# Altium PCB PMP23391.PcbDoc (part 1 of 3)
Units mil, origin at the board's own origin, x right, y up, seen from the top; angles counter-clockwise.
Board outline 5500 x 3250 mil, 2 copper layers (Top Layer, Bottom Layer), stack 62 mil thick; 163 components, 101 nets, 543 pads, 307 vias.
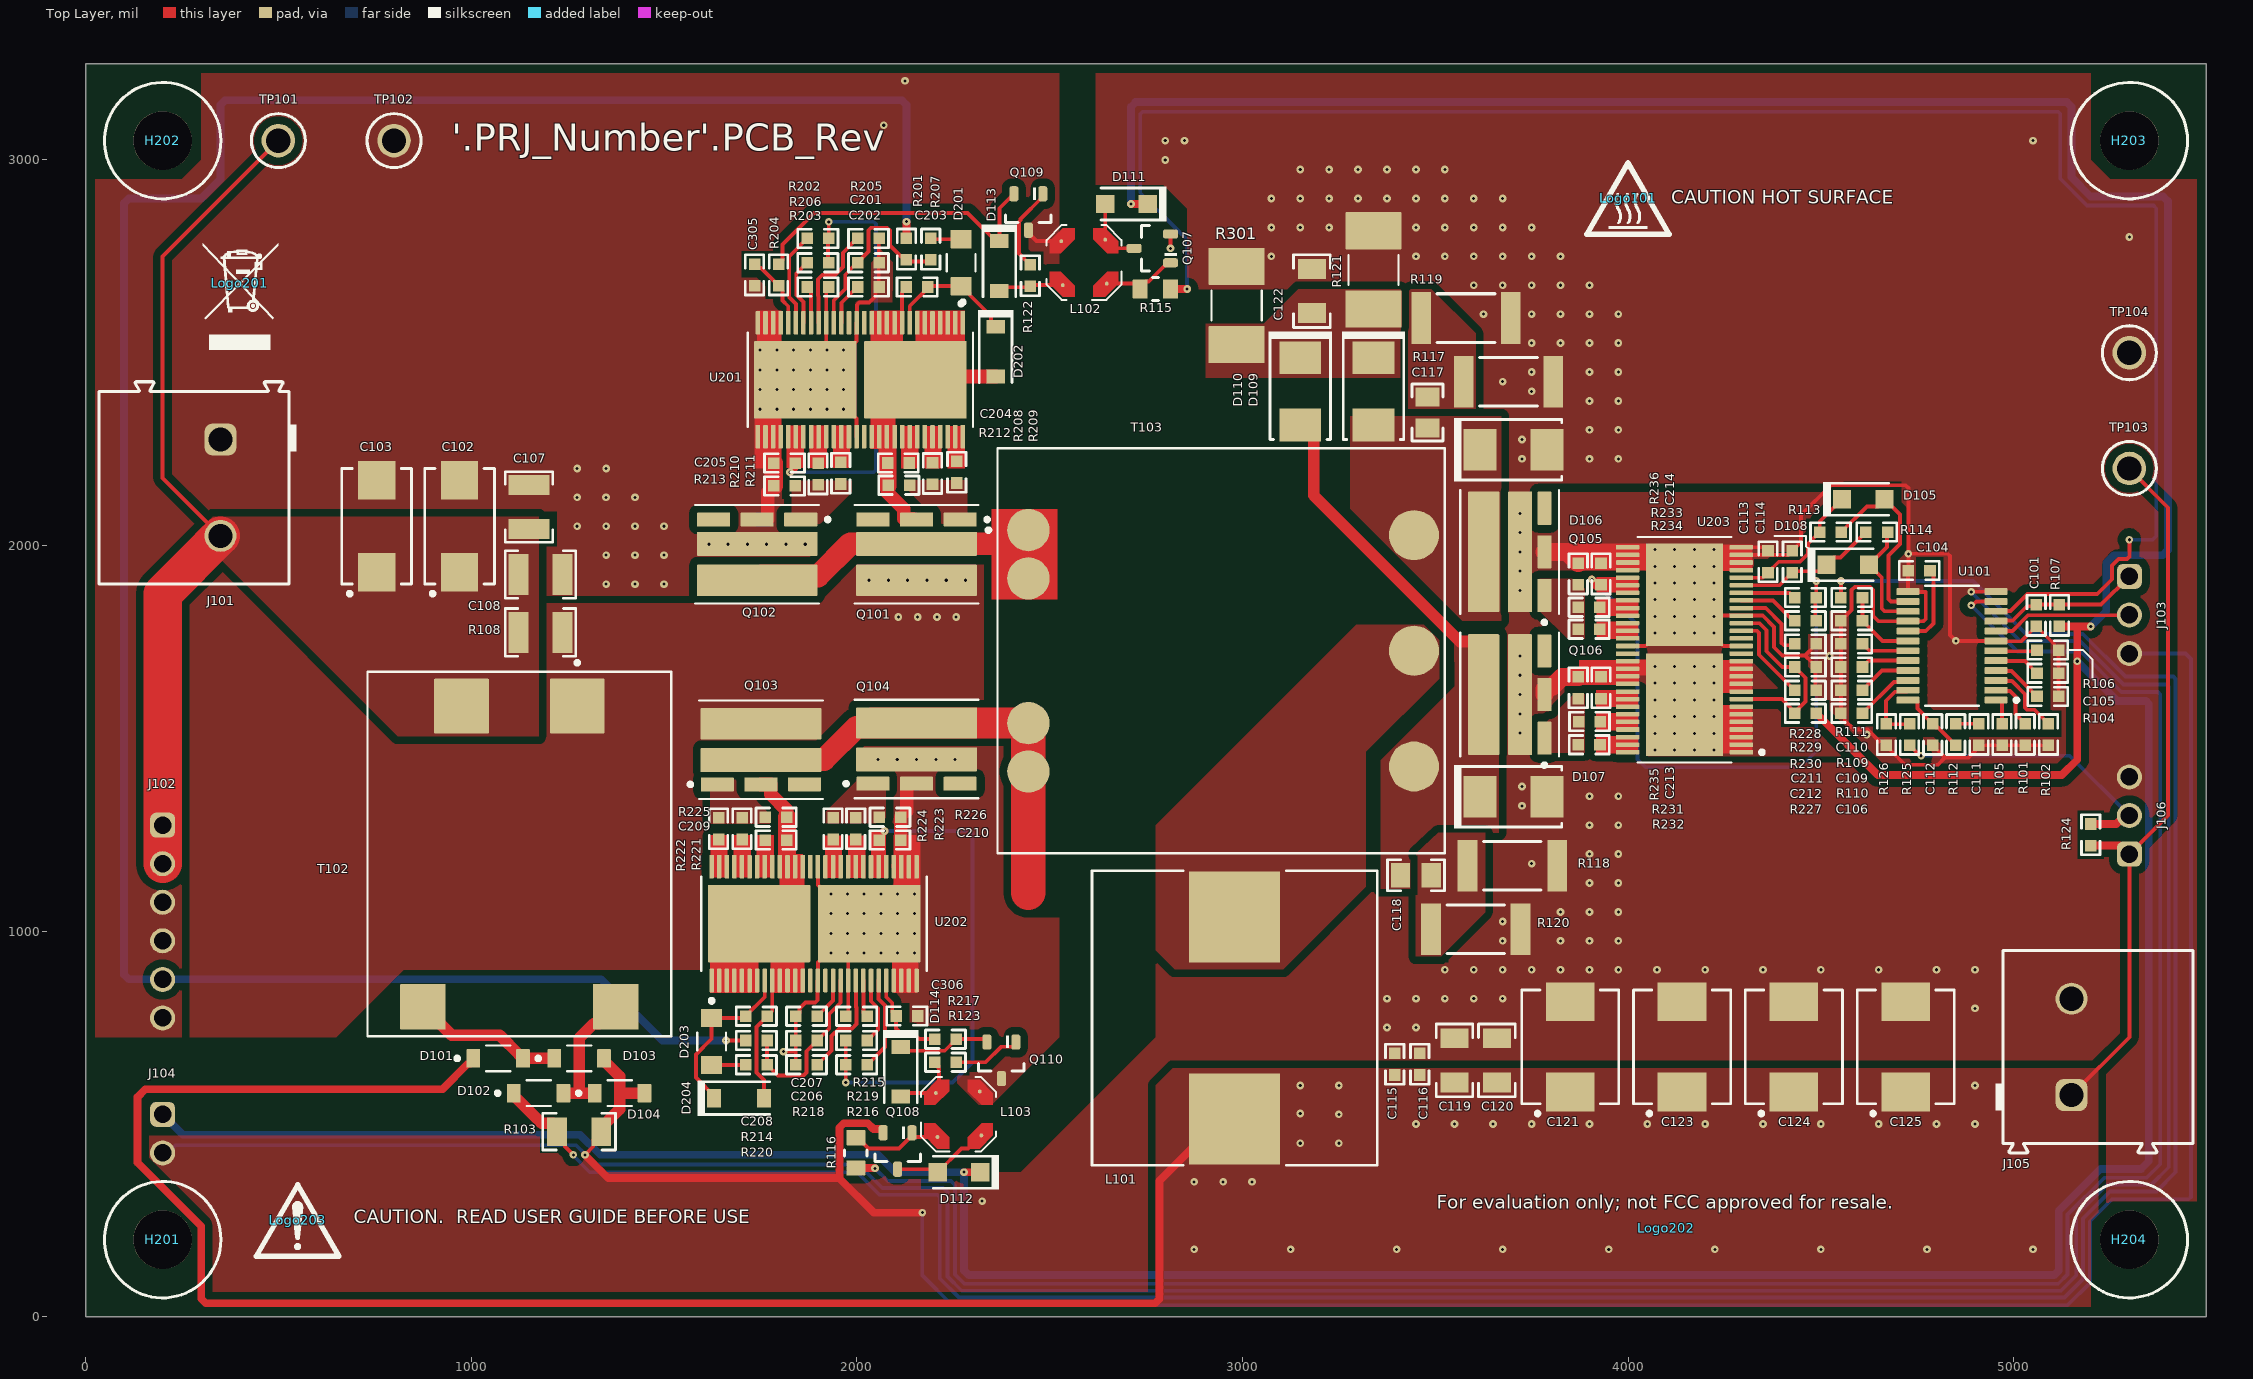
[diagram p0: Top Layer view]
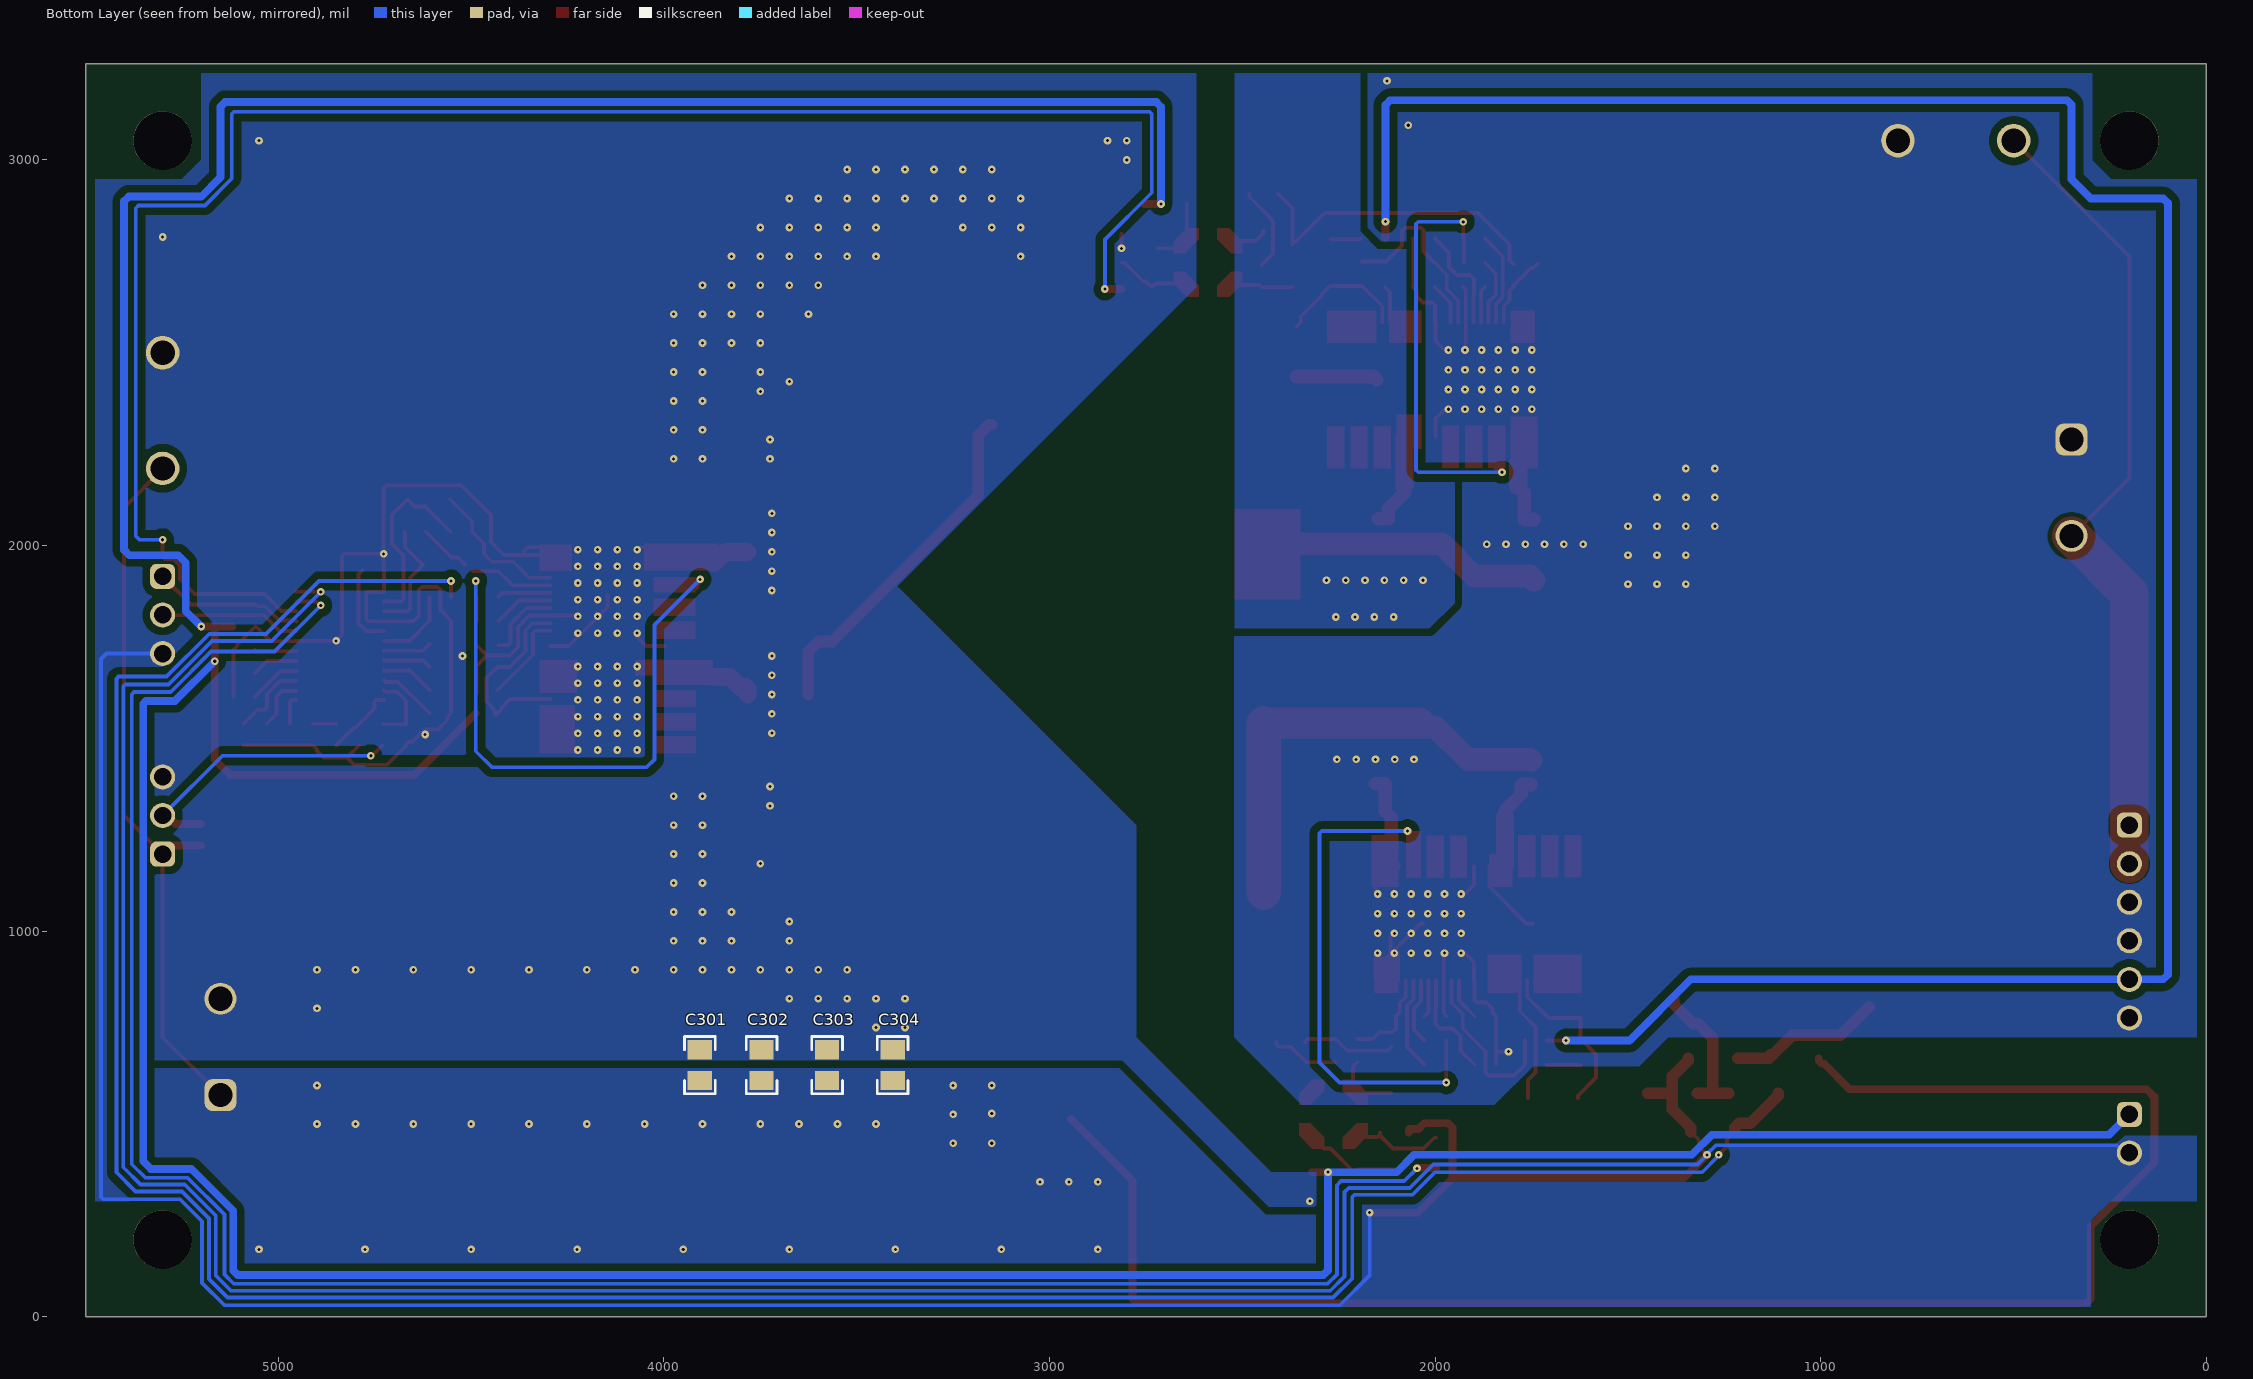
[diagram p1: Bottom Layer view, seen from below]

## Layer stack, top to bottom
Top Solder: solder mask 0.4, Solder Resist, Dk 3.5
Top Layer: signal copper 1.4
Dielectric1: core 59.2, FR-4 High Tg, Dk 4.8
Bottom Layer: signal copper 1.4
Bottom Solder: solder mask 0.4, Solder Resist, Dk 3.5

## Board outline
0,0 0,3250 5500,3250 5500,0

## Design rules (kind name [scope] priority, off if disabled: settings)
AcuteAngle [All] p1: minimum=4.50000000000000E+0001 checktracksonly=FALSE
AssemblyTestPointUsage [All] p1: valid=2
BoardOutlineClearance BoardOutlineClearance_MountingHoles [OnCopper and InComponentClass('Mounting Holes')] p1: gap=25 ignorepadtopadclearanceinfootprint=FALSE
BoardOutlineClearance BoardOutlineClearance_Poly [OnCopper and InPoly] p2: gap=25 ignorepadtopadclearanceinfootprint=FALSE
BoardOutlineClearance [OnCopper and Not InComponentClass('Logo') and not InComponentClass('FiducialMark') and not InRegion(1000,500,4000,800)] p3: gap=25 ignorepadtopadclearanceinfootprint=FALSE
Clearance Clearance_2 [InNetClass('HV') vs Not InNetClass('HV')] p1: gap=60 ignorepadtopadclearanceinfootprint=FALSE
Clearance Clearance_1 [InNetClass('MV') vs Not InNetClass('MV')] p2: gap=30 ignorepadtopadclearanceinfootprint=FALSE
Clearance Clearance_Keepouts [((IsTrack Or IsArc) And Not InPoly) And IsFree and IsKeepOut vs ((IsTrack Or IsArc) And Not InPoly) And IsFree and IsKeepOut] p3: gap=0 ignorepadtopadclearanceinfootprint=FALSE
Clearance Clearance_BoardEdge_MountingHoles [OnCopper and InComponentClass('Mounting Holes') vs IsKeepOut] p4: gap=40 ignorepadtopadclearanceinfootprint=FALSE except(0: Arc-Hole Track-Hole SMDPad-Hole THPad-Hole Via-Hole Fill-Hole Poly-Hole Region-Hole Text-Hole)
Clearance Clearance_BoardEdge_Poly [OnCopper and InPoly vs IsKeepOut] p5: gap=50 ignorepadtopadclearanceinfootprint=FALSE except(0: Arc-Hole Track-Hole SMDPad-Hole THPad-Hole Via-Hole Fill-Hole Poly-Hole Region-Hole Text-Hole)
Clearance Clearance_BoardEdge [OnCopper and Not InComponentClass('Logo') and not InComponentClass('FiducialMark') and not InRegion(1000,500,4000,800) and Not IsKeepout vs IsKeepOut] p6: gap=50 ignorepadtopadclearanceinfootprint=FALSE
Clearance Clearance_Poly [InPolygon] p7: gap=20 ignorepadtopadclearanceinfootprint=FALSE except(0: Arc-Hole Track-Hole SMDPad-Hole THPad-Hole Via-Hole Fill-Hole Poly-Hole Region-Hole Text-Hole)
Clearance [All] p8: gap=7.87 ignorepadtopadclearanceinfootprint=FALSE except(0: Arc-Hole Track-Hole SMDPad-Hole THPad-Hole Via-Hole Fill-Hole Poly-Hole Region-Hole Text-Hole)
ComponentClearance [InComponent('T101') vs InComponent('T102')] p1: gap=0 collisioncheckmode=3 verticalgap=100000 showdistances=TRUE
ComponentClearance ComponentClearance_2 [All] p2: gap=10 collisioncheckmode=3 verticalgap=10 showdistances=FALSE
ComponentClearance ComponentClearance_1 [InComponent('T101')] p3: gap=0 collisioncheckmode=3 verticalgap=0 showdistances=FALSE
ComponentClearance ComponentClearance_MountingHoles_FiducialMarks [InComponentClass('Mounting Holes') vs InComponentClass('FiducialMark')] p4: gap=20 collisioncheckmode=3 verticalgap=10 showdistances=FALSE
ComponentClearance ComponentClearance_Shunt [InComponentClass('Header') vs InComponentClass('Shunt')] p5: gap=0 collisioncheckmode=3 verticalgap=0 showdistances=FALSE
ComponentClearance ComponentClearance_Logo [InComponentClass('Logo')] p6: gap=5 collisioncheckmode=3 verticalgap=10 showdistances=FALSE
ComponentClearance ComponentClearance_ScrewToNut [(HasFootprint('NY PMS 440 0025 PH')) vs (HasFootprint('Keystone_1902C'))] p7: gap=20 collisioncheckmode=3 verticalgap=100000 showdistances=FALSE
ComponentClearance ComponentClearance_MountingHoles [InComponentClass('Mounting Holes')] p8: gap=20 collisioncheckmode=3 verticalgap=10 showdistances=FALSE
ComponentClearance ComponentClearance_SmallPassives [HasFootprint('0201*') or HasFootprint('0402*') or HasFootprint('0508') or HasFootprint('0603*') or HasFootprint('0612') or HasFootprint('0805*') or HasFootprint('0815*') or HasFootprint('0830*') or HasFootprint('1206*') or HasFootprint('1210*') or HasFootprint('1808*') or HasFootprint('1812*') or HasFootprint('1825*') or HasFootprint('2010*') or HasFootprint('2220*') or HasFootprint('2225*') or HasFootprint('2512*') or HasFootprint('2728*') or HasFootprint('3518*') vs HasFootprint('0201*') or HasFootprint('0402*') or HasFootprint('0508') or HasFootprint('0603*') or HasFootprint('0612') or HasFootprint('0805*') or HasFootprint('0815*') or HasFootprint('0830*') or HasFootprint('1206*') or HasFootprint('1210*') or HasFootprint('1808*') or HasFootprint('1812*') or HasFootprint('1825*') or HasFootprint('2010*') or HasFootprint('2220*') or HasFootprint('2225*') or HasFootprint('2512*') or HasFootprint('2728*') or HasFootprint('3518*')] p9: gap=20 collisioncheckmode=3 verticalgap=20 showdistances=FALSE
ComponentClearance ComponentClearance_THtoSMT [IsThruComponent vs IsSMTComponent] p10: gap=10 collisioncheckmode=3 verticalgap=10 showdistances=FALSE
ComponentClearance ComponentClearance_THtoTH [IsThruComponent vs IsThruComponent] p11: gap=10 collisioncheckmode=3 verticalgap=10 showdistances=FALSE
DiffPairsRouting [All] p1: maxlimit=100 minlimit=10 mostfreqgap=10 toplayer_minwidth=15 toplayer_maxwidth=15 toplayer_prefwidth=15 bottomlayer_minwidth=15 bottomlayer_maxwidth=15 bottomlayer_prefwidth=15 maxuncoupledlength=1000
FabricationTestPointUsage TestPointUsage [All] p1: valid=2 allowmultiple=FALSE
FabricationTestpoint Testpoint [All] p1: side=3 testpointundercomponent=TRUE minsize=40 maxsize=100 preferedsize=60 minholesize=0 maxholesize=40 preferedholesize=32 testpointgrid=1 allowsidetop=TRUE allowsidebottom=TRUE usegrid=TRUE gridtolerance=0.01
FanoutControl Fanout_LCC [IsLCC] p1: bgadir=Out bgaviamode=Centered fanoutstyle=Auto fanoutdirection=Alternating viagrid=1 // Fanout_LCC (Default Rule)
FanoutControl Fanout_BGA [IsBGA] p2: bgadir=Out bgaviamode=Centered fanoutstyle=Auto fanoutdirection=Alternating viagrid=1 // Fanout_BGA (Default Rule)
FanoutControl Fanout_Default [All] p4: bgadir=Out bgaviamode=Centered fanoutstyle=Auto fanoutdirection=Alternating viagrid=1 // Fanout_Default (Default Rule)
FanoutControl Fanout_Small [(CompPinCount < 5)] p5: bgadir=Out bgaviamode=Centered fanoutstyle=Auto fanoutdirection=OutThenIn viagrid=1 // Fanout_Small (Default Rule)
Height [All] p1: minheight=0 maxheight=3000 prefheight=500
HoleSize [All] p1: absolutevalues=TRUE maxlimit=251 minlimit=7.87 maxpercent=80.000 minpercent=20.000
MinimumAnnularRing MinimumAnnularRing_ThermalPadVias [IsVia and InAnyComponent] p1: minimumring=5.91
MinimumAnnularRing [All] p2: minimumring=8
MinimumSolderMaskSliver MinimumSolderMaskSliver_Logo [InComponentClass('Logo') vs InComponentClass('Logo')] p1: minsoldermaskwidth=0.7
MinimumSolderMaskSliver [All] p2: minsoldermaskwidth=3.94
PlaneConnect [All] p1: planeconnectstyle=Direct reliefexpansion=10 reliefentries=4 reliefconductorwidth=10 reliefairgap=10
PolygonConnect PolygonConnect_15 [All vs IsNamedPolygon('C109_2') Or  IsNamedPolygon('C107_2') Or  IsNamedPolygon('HV') Or  IsNamedPolygon('Q203_5') Or  IsNamedPolygon('C107_2') Or  IsNamedPolygon('HS') Or  IsNamedPolygon('Q201_5') Or  IsNamedPolygon('Q203_5') Or  IsNamedPolygon('C106_2') Or  IsNamedPolygon('C108_2') Or  IsNamedPolygon('Vout') Or  IsNamedPolygon('Q203_5') Or  IsNamedPolygon('C108_2') Or  IsNamedPolygon('C113_2') Or  IsNamedPolygon('Q203_5') Or  IsNamedPolygon('Q201_5') Or  IsNamedPolygon('C107_2') Or  IsNamedPolygon('C102_1') Or  IsNamedPolygon('SGND') Or  IsNamedPolygon('GND') Or  IsNamedPolygon('SGND') Or  IsNamedPolygon('GND') Or  IsNamedPolygon('IN+') Or  IsNamedPolygon('IN+') Or  IsNamedPolygon('Q201_5') Or  IsNamedPolygon('Q201_5') Or  IsNamedPolygon('SGND') Or  IsNamedPolygon('SGND') Or  IsNamedPolygon('Vout') Or  IsNamedPolygon('Vout') Or  IsNamedPolygon('IN+') Or  IsNamedPolygon('GND') Or  IsNamedPolygon('IN+') Or  IsNamedPolygon('GND')] p1: connectstyle=Direct reliefconductorwidth=10 reliefentries=4 polygonreliefangle="90 Angle" airgapwidth=10
PolygonConnect PolygonConnect_14 [All vs IsNamedPolygon('C106_2') Or  IsNamedPolygon('C107_2') Or  IsNamedPolygon('C107_2') Or  IsNamedPolygon('C107_2') Or  IsNamedPolygon('C102_1') Or  IsNamedPolygon('Q203_5') Or  IsNamedPolygon('Vout') Or  IsNamedPolygon('Q203_5') Or  IsNamedPolygon('Q203_5') Or  IsNamedPolygon('Q201_5') Or  IsNamedPolygon('C108_2') Or  IsNamedPolygon('Q203_5') Or  IsNamedPolygon('HS') Or  IsNamedPolygon('HV') Or  IsNamedPolygon('C108_2') Or  IsNamedPolygon('Q201_5') Or  IsNamedPolygon('C109_2') Or  IsNamedPolygon('Q201_5') Or  IsNamedPolygon('Q201_5') Or  IsNamedPolygon('C113_2')] p2: connectstyle=Direct reliefconductorwidth=10 reliefentries=4 polygonreliefangle="90 Angle" airgapwidth=10
PolygonConnect PolygonConnect_13 [All vs IsNamedPolygon('C102_1') Or  IsNamedPolygon('HV') Or  IsNamedPolygon('C107_2') Or  IsNamedPolygon('C109_2') Or  IsNamedPolygon('C107_2') Or  IsNamedPolygon('C108_2') Or  IsNamedPolygon('C106_2') Or  IsNamedPolygon('C108_2') Or  IsNamedPolygon('C113_2') Or  IsNamedPolygon('C107_2')] p3: connectstyle=Direct reliefconductorwidth=10 reliefentries=4 polygonreliefangle="90 Angle" airgapwidth=10
PolygonConnect PolygonConnect_12 [All vs IsNamedPolygon('C107_2') Or  IsNamedPolygon('C113_2') Or  IsNamedPolygon('C106_2') Or  IsNamedPolygon('C107_2') Or  IsNamedPolygon('C107_2') Or  IsNamedPolygon('C102_1')] p4: connectstyle=Direct reliefconductorwidth=10 reliefentries=4 polygonreliefangle="90 Angle" airgapwidth=10
PolygonConnect PolygonConnect_11 [All vs IsNamedPolygon('C106_2') Or  IsNamedPolygon('C102_1') Or  IsNamedPolygon('C107_2') Or  IsNamedPolygon('C107_2') Or  IsNamedPolygon('C107_2')] p5: connectstyle=Direct reliefconductorwidth=10 reliefentries=4 polygonreliefangle="90 Angle" airgapwidth=10
PolygonConnect PolygonConnect_10 [All vs IsNamedPolygon('C106_2')] p6: connectstyle=Direct reliefconductorwidth=10 reliefentries=4 polygonreliefangle="90 Angle" airgapwidth=10
PolygonConnect PolygonConnect_9 [All vs IsNamedPolygon('C11_1') Or  IsNamedPolygon('Vin') Or  IsNamedPolygon('Vin') Or  IsNamedPolygon('5V') Or  IsNamedPolygon('D6_2') Or  IsNamedPolygon('Q3_3') Or  IsNamedPolygon('GND2') Or  IsNamedPolygon('GND2') Or  IsNamedPolygon('GND') Or  IsNamedPolygon('Q3_4') Or  IsNamedPolygon('12V5') Or  IsNamedPolygon('GND') Or  IsNamedPolygon('12V5') Or  IsNamedPolygon('D3_1')] p7: connectstyle=Direct reliefconductorwidth=10 reliefentries=4 polygonreliefangle="90 Angle" airgapwidth=10
PolygonConnect PolygonConnect_8 [All vs IsNamedPolygon('C11_1') Or  IsNamedPolygon('Vin') Or  IsNamedPolygon('12V5') Or  IsNamedPolygon('Q3_3') Or  IsNamedPolygon('GND2') Or  IsNamedPolygon('GND2') Or  IsNamedPolygon('5V') Or  IsNamedPolygon('Q3_4') Or  IsNamedPolygon('12V5')] p8: connectstyle=Direct reliefconductorwidth=10 reliefentries=4 polygonreliefangle="90 Angle" airgapwidth=10
PolygonConnect PolygonConnect_7 [All vs IsNamedPolygon('GND2') Or  IsNamedPolygon('GND2') Or  IsNamedPolygon('5V') Or  IsNamedPolygon('12V5') Or  IsNamedPolygon('12V5') Or  IsNamedPolygon('C11_1')] p9: connectstyle=Direct reliefconductorwidth=10 reliefentries=4 polygonreliefangle="90 Angle" airgapwidth=10
PolygonConnect PolygonConnect_6 [All vs IsNamedPolygon('GND2') Or  IsNamedPolygon('SGND') Or  IsNamedPolygon('GND1') Or  IsNamedPolygon('C901_1') Or  IsNamedPolygon('SGND') Or  IsNamedPolygon('GND2') Or  IsNamedPolygon('GND1')] p10: connectstyle=Direct reliefconductorwidth=10 reliefentries=4 polygonreliefangle="90 Angle" airgapwidth=10
PolygonConnect PolygonConnect_5 [All vs IsNamedPolygon('GND1') Or  IsNamedPolygon('GND1')] p11: connectstyle=Direct reliefconductorwidth=10 reliefentries=4 polygonreliefangle="90 Angle" airgapwidth=10
PolygonConnect PolygonConnect_4 [All vs IsNamedPolygon('C21_1') Or  IsNamedPolygon('C5_1') Or  IsNamedPolygon('C12_2') Or  IsNamedPolygon('C2_2') Or  IsNamedPolygon('C13_1') Or  IsNamedPolygon('C28_1') Or  IsNamedPolygon('C6_1') Or  IsNamedPolygon('GND') Or  IsNamedPolygon('GND2') Or  IsNamedPolygon('C14_1') Or  IsNamedPolygon('C13_1') Or  IsNamedPolygon('Q1_3') Or  IsNamedPolygon('C14_1') Or  IsNamedPolygon('C5_1') Or  IsNamedPolygon('GND2') Or  IsNamedPolygon('C28_1') Or  IsNamedPolygon('D5_2') Or  IsNamedPolygon('D6_2') Or  IsNamedPolygon('D2_1') Or  IsNamedPolygon('C12_2') Or  IsNamedPolygon('D2_1') Or  IsNamedPolygon('C4_1') Or  IsNamedPolygon('C4_1') Or  IsNamedPolygon('C2_2') Or  IsNamedPolygon('GND') Or  IsNamedPolygon('C33_1') Or  IsNamedPolygon('C9_1')] p12: connectstyle=Direct reliefconductorwidth=10 reliefentries=4 polygonreliefangle="90 Angle" airgapwidth=10
PolygonConnect PolygonConnect_3 [All vs IsNamedPolygon('C28_1') Or  IsNamedPolygon('C12_2') Or  IsNamedPolygon('C28_1') Or  IsNamedPolygon('C9_1') Or  IsNamedPolygon('D5_2') Or  IsNamedPolygon('C12_2') Or  IsNamedPolygon('C2_2') Or  IsNamedPolygon('C14_1') Or  IsNamedPolygon('C4_1') Or  IsNamedPolygon('C14_1') Or  IsNamedPolygon('D6_2') Or  IsNamedPolygon('GND2') Or  IsNamedPolygon('Q1_3') Or  IsNamedPolygon('C5_1') Or  IsNamedPolygon('D2_1') Or  IsNamedPolygon('C4_1') Or  IsNamedPolygon('C13_1') Or  IsNamedPolygon('C5_1') Or  IsNamedPolygon('C13_1') Or  IsNamedPolygon('C33_1') Or  IsNamedPolygon('D2_1') Or  IsNamedPolygon('GND') Or  IsNamedPolygon('GND') Or  IsNamedPolygon('GND2') Or  IsNamedPolygon('C2_2') Or  IsNamedPolygon('C6_1') Or  IsNamedPolygon('C21_1')] p13: connectstyle=Direct reliefconductorwidth=10 reliefentries=4 polygonreliefangle="90 Angle" airgapwidth=10
PolygonConnect PolygonConnect_2 [All vs IsNamedPolygon('C21_1') Or  IsNamedPolygon('C4_1') Or  IsNamedPolygon('D5_2') Or  IsNamedPolygon('C5_1') Or  IsNamedPolygon('C14_1') Or  IsNamedPolygon('C13_1') Or  IsNamedPolygon('C4_1') Or  IsNamedPolygon('C33_1') Or  IsNamedPolygon('C12_2') Or  IsNamedPolygon('D2_1') Or  IsNamedPolygon('C2_2') Or  IsNamedPolygon('C28_1') Or  IsNamedPolygon('C12_2') Or  IsNamedPolygon('D2_1') Or  IsNamedPolygon('C5_1') Or  IsNamedPolygon('Q1_3') Or  IsNamedPolygon('GND') Or  IsNamedPolygon('D6_2') Or  IsNamedPolygon('C6_1') Or  IsNamedPolygon('C2_2') Or  IsNamedPolygon('C14_1') Or  IsNamedPolygon('C28_1') Or  IsNamedPolygon('C13_1') Or  IsNamedPolygon('C9_1') Or  IsNamedPolygon('GND')] p14: connectstyle=Direct reliefconductorwidth=10 reliefentries=4 polygonreliefangle="90 Angle" airgapwidth=10
PolygonConnect PolygonConnect_1 [All vs IsNamedPolygon('C28_1') Or  IsNamedPolygon('D5_2') Or  IsNamedPolygon('C5_1') Or  IsNamedPolygon('C5_1') Or  IsNamedPolygon('D2_1') Or  IsNamedPolygon('C21_1') Or  IsNamedPolygon('C9_1') Or  IsNamedPolygon('C4_1') Or  IsNamedPolygon('C14_1') Or  IsNamedPolygon('C28_1') Or  IsNamedPolygon('C6_1') Or  IsNamedPolygon('C12_2') Or  IsNamedPolygon('C33_1') Or  IsNamedPolygon('C4_1') Or  IsNamedPolygon('C13_1') Or  IsNamedPolygon('C12_2') Or  IsNamedPolygon('D6_2') Or  IsNamedPolygon('C2_2') Or  IsNamedPolygon('C14_1') Or  IsNamedPolygon('D2_1') Or  IsNamedPolygon('C2_2') Or  IsNamedPolygon('C13_1')] p15: connectstyle=Direct reliefconductorwidth=10 reliefentries=4 polygonreliefangle="90 Angle" airgapwidth=10
PolygonConnect [All] p16: connectstyle=Direct reliefconductorwidth=10 reliefentries=4 polygonreliefangle="90 Angle" airgapwidth=10
RoutingVias ThermalPadVias [IsVia and InAnyComponent] p1: holewidth=7.87 width=19.68 viastyle="Through Hole" minholewidth=7.87 minwidth=19.68 maxholewidth=12.99 maxwidth=23.62
RoutingVias [All] p2: holewidth=16 width=34 viastyle="Through Hole" minholewidth=7.87 minwidth=20 maxholewidth=40 maxwidth=65
SilkToBoardRegionClearance [Not ((IsComment or IsDesignator) And (Hide <> 'False')) and not InRegion(1000,500,4000,800)] p1:
SilkToSilkClearance SilkToSilkClearance_Pb-FreeLogo [(HasFootprint('Pb-Free_Overlay_Medium') OR HasFootprint('Pb-Free_Overlay_Small')) vs (HasFootprint('Pb-Free_Overlay_Medium') OR HasFootprint('Pb-Free_Overlay_Small'))] p1: silktosilkclearance=0
SilkToSilkClearance [All] p2: silktosilkclearance=4
SilkToSolderMaskClearance SilkToComponentPadClearance [IsPad and InAnycomponent] p1: minsilkscreentomaskgap=5 clearancetoexposedcopper=TRUE
SilkToSolderMaskClearance "Silk to Solder Mask Opening" [All] p2: minsilkscreentomaskgap=4 clearancetoexposedcopper=FALSE
SolderMaskExpansion [All] p1: expansion=1.97 istentingtop=FALSE
SupplyNets "Schematic Supply Nets_5" [InNet('+12Vs')] p1: voltage=0.000
SupplyNets "Schematic Supply Nets_4" [InNet('VIN')] p2: voltage=0.000
SupplyNets "Schematic Supply Nets_3" [InNet('SGND')] p3: voltage=0.000
SupplyNets "Schematic Supply Nets_2" [InNet('VOUT')] p4: voltage=0.000
SupplyNets "Schematic Supply Nets_1" [InNet('PGND')] p5: voltage=0.000
SupplyNets "Schematic Supply Nets" [InNet('+12Vp')] p6: voltage=0.000
Width [All] p1: maxlimit=100 minlimit=6 preferedwidth=10 checkconnectedcopper=TRUE
14 further rules are at their usual default settings.

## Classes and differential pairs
component class "PMP23391 Drivers": !PCB201 C201 C202 C203 C204 C205 C206 C207 C208 C209 C210 C211 C212 C213 C214 C305 C306 D201 D202 D203 D204 H201 H202 H203 H204 Logo201 Logo202 Logo203 R201 R202 R203 R204 R205 R206 R207 R208 R209 R210 R211 R212 R213 R214 R215 R216 R217 R218 R219 R220 R221 R222 R223 R224 R225 R226 R227 R228 R229 R230 R231 R232 R233 R234 R235 R236 U201 U202 U203
component class Header: J102 J103 J104 J106

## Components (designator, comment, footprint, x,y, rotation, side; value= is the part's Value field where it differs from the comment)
C101 "GRM188R71E105KA12D" 0603_HV 5058.6,1818.89 r270 top value=1uF
C102 "T494X226K050AT" 7343-43 970,2050 r90 top value=22uF
C103 "T494X226K050AT" 7343-43 755,2050 r90 top value=22uF
C104 "GRM188Z71C225KE43" 0603_HV 4755,1935 r0 top value=2.2uF
C105 "GRM188R71E562KA01D" 0603_HV 5088.6,1668.89 r180 top value=5600pF
C106 "GCM188R71E104KA57D" 0603_HV 4580,1565 r180 top value=0.1uF
C107 "GCM32EL8EH106KA07L" 1210_270 1150,2100 r90 top value=10uF
C108 "GCM32EL8EH106KA07L" 1210_270 1180,1925 r0 top value=10uF
C109 "GCM188R71C474KA55D" 0603_HV 4580,1685 r0 top value=0.47uF
C110 "GCM1885C2A100JA16D" 0603_HV 4580,1805 r180 top value=10pF
C111 "GRM188R71E682KA01D" 0603_HV 4910,1510 r270 top value=6800pF
C112 "GRM1885C1H121JA01D" 0603_HV 4790,1510 r270 top value=120pF
C113 "GRM1885C1H101JA01D" 0603_HV 4362.91,1958.05 r270 top value=100pF
C114 "GRM1885C1H101JA01D" 0603_HV 4425.91,1958.05 r270 top value=100pF
C115 "GRM188R71E105KA12D" 0603_HV 3395,655 r90 top value=1uF
C116 "GRM188R71E105KA12D" 0603_HV 3460,655 r90 top value=1uF
C117 "GRM2165C2A122JA01D" 0805_HV 3480,2345 r90 top value=1200pF
C118 "GRM2165C2A122JA01D" 0805_HV 3450,1145 r0 top value=1200pF
C119 "GRM31CR71E106MA12L" 1206 3550,665 r90 top value=10uF
C120 "GRM31CR71E106MA12L" 1206 3660,665 r90 top value=10uF
C121 "TPSV107K025R0100" 7361-38 3850,700 r90 top value=100uF
C122 "GRM319R72A104KA01D" 1206 3180,2660 r90 top value=0.1uF
C123 "TPSV107K025R0100" 7361-38 4140,700 r90 top value=100uF
C124 "TPSV107K025R0100" 7361-38 4430,700 r90 top value=100uF
C125 "TPSV107K025R0100" 7361-38 4720,700 r90 top value=100uF
C201 "GRM188R71E105KA12D" 0603_HV 2030.33,2733.41 r0 top value=1uF
C202 "GRM188R71E105KA12D" 0603_HV 2030.33,2670.41 r180 top value=1uF
C203 "C0603C104K5RACAUTO" 0603_HV 2156.31,2670.41 r180 top value=0.1uF
C204 "GRM188R71E105KA12D" 0603_HV 2107.76,2214.16 r180 top value=1uF
C205 "GRM188Z71C225KE43" 0603_HV 1812.48,2213.72 r0 top value=2.2uF
C206 "GRM188R71E105KA12D" 0603_HV 1869.57,716.59 r180 top value=1uF
C207 "GRM188R71E105KA12D" 0603_HV 1869.57,779.59 r0 top value=1uF
C208 "C0603C104K5RACAUTO" 0603_HV 1739.65,779.59 r0 top value=0.1uF
C209 "GRM188R71E105KA12D" 0603_HV 1790.83,1236.28 r0 top value=1uF
C210 "GRM188Z71C225KE43" 0603_HV 2086.1,1236.28 r180 top value=2.2uF
C211 "GRM188R71E105KA12D" 0603_HV 4460,1685 r0 top value=1uF
C212 "GRM188R71E105KA12D" 0603_HV 4460,1625 r180 top value=1uF
C213 "GRM188Z71C225KE43" 0603_HV 3929.84,1631.28 r270 top value=2.2uF
C214 "GRM188Z71C225KE43" 0603_HV 3929.84,1926.55 r270 top value=2.2uF
C301 "GRM21BR71E475KA73L" 0805_HV 3907,652.65 r90 bottom value=4.7uF
C302 "GRM21BR71E475KA73L" 0805_HV 3747,652.65 r90 bottom value=4.7uF
C303 "GRM21BR71E475KA73L" 0805_HV 3577,652.65 r90 bottom value=4.7uF
C304 "GRM21BR71E475KA73L" 0805_HV 3407,652.65 r90 bottom value=4.7uF
C305 "GRM1885C1H101JA01D" 0603_HV 1735,2701.91 r90 top value=100pF
C306 "GRM1885C1H101JA01D" 0603_HV 2130,780 r180 top value=100pF
D101 "BAT46GWJ" FP-BAT46GWJ_SOD-123-MFG 1070,670 r0 top
D102 "BAT46GWJ" FP-BAT46GWJ_SOD-123-MFG 1175,580 r0 top
D103 "BAT46GWJ" FP-BAT46GWJ_SOD-123-MFG 1280,670 r0 top
D104 "BAT46GWJ" FP-BAT46GWJ_SOD-123-MFG 1385,580 r0 top
D105 "PMEG4030ER,115" SOD-123W 4610,2120 r0 top value=40V
D106 "MBRS1100T3G" SMB 3703.19,2248.64 r0 top value=100V
D107 "MBRS1100T3G" SMB 3703.19,1348.64 r0 top value=100V
D108 "PMEG4030ER,115" SOD-123W 4570,1950 r0 top value=40V
D109 "MBRS1100T3G" SMB 3340,2400 r270 top value=100V
D110 "MBRS1100T3G" SMB 3150,2400 r270 top value=100V
D111 "PMEG4030ER,115" SOD-123W 2699.21,2885.7 r180 top value=40V
D112 "PMEG4030ER,115" SOD-123W 2265,375 r180 top value=40V
D113 "1N4148W-TP" SOD-123 2370,2724.88 r270 top value=100V
D114 "1N4148W-TP" SOD-123 2114.1,635.44 r270 top value=100V
D201 "SS1H20LW" FP-SS1H20LW_SOD-123W-MFG 2270.49,2733.41 r90 top
D202 "MMSZ5243B-7-F" SOD-123 2360,2503.01 r270 top value=13V
D203 "SS1H20LW" FP-SS1H20LW_SOD-123W-MFG 1623.5,713.8 r270 top
D204 "MMSZ5243B-7-F" SOD-123 1694.6,567.33 r0 top value=13V
H201 "4824" KEYSTONE_4824 200,200 r0 top
H202 "4824" KEYSTONE_4824 200,3050 r0 top
H203 "4824" KEYSTONE_4824 5300,3050 r0 top
H204 "4824" KEYSTONE_4824 5300,200 r0 top
J101 "OSTT7020150" On-Shore_OSTT7020150 350,2150 r270 top
J102 "61300611121" WURTH_61300611121 200,1025 r270 top
J103 "61300311121" WURTH_61300311121 5300,1820 r270 top
J104 "61300211121" WURTH_61300211121 200,475 r270 top
J105 "OSTT7020150" On-Shore_OSTT7020150 5150,700 r90 top
J106 "61300311121" WURTH_61300311121 5300,1300 r90 top
L101 "7443556130" WE-HCB_1890 2980,775 r270 top value=1.3uH
L102 "LPD4012-223MRB" LPD4012 2589.21,2734.33 r180 top value=22uH
L103 "LPD4012-223MRB" LPD4012 2264,525.33 r90 top value=22uH
Logo101 "CAUTION HOT SURFACE" IEC_HotSurface_Small 4000,2900 r0 top
Logo201 "WEEE logo" WEEE_Minimum 400,2680 r0 top
Logo202 "FCC disclaimer" FCC_disclaimer 4098.93,230 r0 top
Logo203 "CAUTION.  READ USER GUIDE BEFORE USE" IEC_Caution_Small 550,250 r0 top
Q101 "EPC7018GC" FP-EPC7018GC_FSMD-G-MFG 2155,1977.5 r0 top
Q102 "EPC7018GC" FP-EPC7018GC_FSMD-G-MFG 1741.61,1977.5 r0 top
Q103 "EPC7018GC" FP-EPC7018GC_FSMD-G-MFG 1751.46,1470.53 r180 top
Q104 "EPC7018GC" FP-EPC7018GC_FSMD-G-MFG 2155,1472.5 r180 top
Q105 "EPC7018GC" FP-EPC7018GC_FSMD-G-MFG 3693.19,1983.64 r270 top
Q106 "EPC7018GC" FP-EPC7018GC_FSMD-G-MFG 3693.19,1613.64 r270 top
Q107 "BSS138" SOT-23 2766.34,2770.82 r180 top value=50V
Q108 "BSS138" SOT-23 2105.79,430 r270 top value=50V
Q109 "MMBT2907A" SOT-23 2445,2865 r270 top value="60 V"
Q110 "MMBT2907A" SOT-23 2375,665 r270 top value="60 V"
R101 "CRCW0603147KFKEA" 0603_HV 5030,1510 r90 top value=147k
R102 "CRCW060375K0FKEA" 0603_HV 5090,1510 r90 top value=75.0k
R103 "CRCW12061R69FKEA" 1206 1280,480 r180 top value=1.69
R104 "CRCW060349K9FKEA" 0603_HV 5088.6,1608.89 r0 top value=49.9k
R105 "RC0603FR-07205KL" 0603_HV 4970,1510 r270 top value=205k
R106 "CRCW06031M00JNEA" 0603_HV 5088.6,1728.89 r180 top value=1.0Meg
R107 "CRCW06030000Z0EA" 0603_HV 5118.6,1818.89 r270 top value=0
R108 "MCR25JZHFLR300" 1210 1180,1775 r0 top value=0.3
R109 "CRCW06030000Z0EA" 0603_HV 4580,1745 r180 top value=0
R110 "CRCW060334K8FKEA" 0603_HV 4580,1625 r180 top value=34.8k
R111 "CRCW06031K50FKEA" 0603_HV 4580,1865 r180 top value=1.50k
R112 "CRCW060330K1FKEA" 0603_HV 4850,1510 r270 top value=30.1k
R113 "CRCW0603100RJNEA" 0603_HV 4525,2035 r0 top value=100
R114 "CRCW0603100RJNEA" 0603_HV 4645,2035 r0 top value=100
R115 "RC0805JR-070RL" 0805_HV1 2774.21,2665.22 r0 top value=0
R116 "RC0805JR-070RL" 0805_HV1 1997.5,425 r270 top value=0
R117 "CRCW251233R0JNEG" 2512 3690,2425 r180 top value=33
R118 "CRCW251233R0JNEG" 2512 3700,1170 r180 top value=33
R119 "CRCW251233R0JNEG" 2512 3580,2590 r180 top value=33
R120 "CRCW251233R0JNEG" 2512 3605,1005 r180 top value=33
R121 "CRM2512-FX-1002ELF" FP-CRM2512-FX-1002ELF_2512-MFG 3340,2715 r90 top value=10k
R122 "CRCW060310K0FKEA" 0603_HV 2450,2699.88 r270 top value=10.0k
R123 "CRCW060310K0FKEA" 0603_HV 2230,660 r180 top value=10.0k
R124 "CRCW060310R0FKEA" 0603_HV 5200,1250 r270 top value=10.0
R125 "CRCW0603115KFKEA" 0603_HV 4730,1510 r270 top value=115k
R126 "CRCW06036K19FKEA" 0603_HV 4670,1510 r90 top value=6.19k
R201 "CRCW06030000Z0EA" 0603_HV 2128.76,2768.84 r270 top value=0
R202 "CRCW06030000Z0EA" 0603_HV 1899.22,2796.4 r180 top value=0
R203 "CRCW0603100KFKEA" 0603_HV 1899.09,2670.41 r180 top value=100k
R204 "CRCW0603100RJNEA" 0603_HV 1797.17,2701.91 r90 top value=100
R205 "CRCW0603100KFKEA" 0603_HV 2030.33,2796.4 r180 top value=100k
R206 "CRCW060310K0FKEA" 0603_HV 1899.09,2733.41 r0 top value=10.0k
R207 "MCT06030C2008FP500" 0603_HV 2191.75,2768.84 r90 top value=2.00
R208 "CRCW06032R49FKEA" 0603_HV 2196.34,2186.8 r90 top value=2.49
R209 "CRCW06032R49FKEA" 0603_HV 2259.35,2190.14 r90 top value=2.49
R210 "CRCW06032R49FKEA" 0603_HV 1899.54,2185.72 r90 top value=2.49
R211 "CRCW06032R49FKEA" 0603_HV 1958.4,2187.59 r90 top value=2.49
R212 "CRCW060310K0FKEA" 0603_HV 2109.28,2156.19 r180 top value=10.0k
R213 "CRCW060310K0FKEA" 0603_HV 1812.48,2154.67 r180 top value=10.0k
R214 "CRCW06030000Z0EA" 0603_HV 1739.65,716.59 r0 top value=0
R215 "CRCW0603100KFKEA" 0603_HV 1999.49,779.59 r0 top value=100k
R216 "CRCW06030000Z0EA" 0603_HV 1999.49,653.6 r0 top value=0
R217 "CRCW0603100RJNEA" 0603_HV 2230,720 r0 top value=100
R218 "CRCW0603100KFKEA" 0603_HV 1869.57,653.6 r0 top value=100k
R219 "CRCW060310K0FKEA" 0603_HV 1999.49,716.59 r180 top value=10.0k
R220 "MCT06030C2008FP500" 0603_HV 1739.65,653.6 r180 top value=2.00
R221 "CRCW06032R49FKEA" 0603_HV 1702.56,1265.77 r270 top value=2.49
R222 "CRCW06032R49FKEA" 0603_HV 1641.61,1265.77 r270 top value=2.49
R223 "CRCW06032R49FKEA" 0603_HV 1997.52,1265.77 r270 top value=2.49
R224 "CRCW06032R49FKEA" 0603_HV 1938.46,1265.77 r270 top value=2.49
R225 "CRCW060310K0FKEA" 0603_HV 1790.83,1295.33 r0 top value=10.0k
R226 "CRCW060310K0FKEA" 0603_HV 2086.1,1295.33 r0 top value=10.0k
R227 "CRCW06030000Z0EA" 0603_HV 4460,1565 r180 top value=0
R228 "CRCW060310K0FKEA" 0603_HV 4460,1865 r0 top value=10.0k
R229 "CRCW06030000Z0EA" 0603_HV 4460,1805 r180 top value=0
R230 "CRCW060349K9FKEA" 0603_HV 4460,1745 r0 top value=49.9k
R231 "CRCW06032R49FKEA" 0603_HV 3900.19,1543.64 r0 top value=2.49
R232 "CRCW06032R49FKEA" 0603_HV 3899.35,1483.64 r0 top value=2.49
R233 "CRCW06032R49FKEA" 0603_HV 3899.04,1839.94 r0 top value=2.49
R234 "CRCW06032R49FKEA" 0603_HV 3899.04,1782.87 r0 top value=2.49
R235 "CRCW060310K0FKEA" 0603_HV 3870.79,1631.28 r90 top value=10.0k
R236 "CRCW060310K0FKEA" 0603_HV 3870.79,1926.55 r90 top value=10.0k
R301 "CRM2512-FX-1002ELF" FP-CRM2512-FX-1002ELF_2512-MFG 2985,2622.5 r90 top value=10k
T102 "63554-R01" FP-63554-R01_SMT_XFRMR_24MM0_20MM0-MFG 1125,1200 r270 top
T103 "CP-D1549-BZ" FP-CP-D1549-BZ_SMT_XFRMR_29MM46_26MM67-MFG 2945,1727.13 r0 top
TP101 "5010" Keystone5010 500,3050 r0 top
TP102 "5011" Keystone5011 800,3050 r0 top
TP103 "5010" Keystone5010 5300,2200 r0 top
TP104 "5011" Keystone5011 5300,2500 r0 top
U101 "TPS7H5005MPWSEP" PW0024A-MFG 4840,1740 r180 top
U201 "TPS7H6005/EM" DCA0056M-MFG 2009.33,2430.26 r270 top
U202 "TPS7H6005/EM" DCA0056M-MFG 1889.25,1019.74 r90 top
U203 "TPS7H6005/EM" DCA0056M-MFG 4146.38,1729.7 r180 top

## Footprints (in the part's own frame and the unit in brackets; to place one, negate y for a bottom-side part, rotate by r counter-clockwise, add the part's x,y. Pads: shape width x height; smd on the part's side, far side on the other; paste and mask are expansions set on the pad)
0603_HV [mil] "Ernesto recommended land pattern.  26 mil between pads."
  rect 30x30 smd: 1(-28,0) 2(28,0)
  silkscreen extent -52,-24 52,24, body extent -34,-19 34,19, height 39
0805_HV [mil] "0805 with 30mil clearance between pads"
  rect 50x63 smd: 1(-40,0) 2(40,0)
  silkscreen extent -74,-40 74,40, body extent -43,-29 43,29, height 57
0805_HV1 [mm] "Custom footprint based on analyzing multiple manufacturer recommendations"
  rrect10% 1x1.25 smd: 1(-1,0) 2(1,0)
  silkscreen extent -0.2,-0.75 0.2,0.75, body extent -1.1,-0.72 1.1,0.73, height 1.45
1206 [mm] "1206 from SM-752 data"
  rect 1.3x1.85 smd: 1(-1.45,0) 2(1.45,0)
  silkscreen extent -2.4,-1.21 2.4,1.21, body extent -1.7,-0.9 1.7,0.9, height 1.35
1210 [mm] "1210 from SM-752 data"
  rect 1.3x2.7 smd: 1(-1.45,0) 2(1.45,0)
  silkscreen extent -2.32,-1.57 2.32,1.57, body extent -1.7,-1.35 1.7,1.35, height 1.35
1210_270 [mm] "1210"
  rect 1.3x2.7 smd: 1(-1.45,0) 2(1.45,0)
  silkscreen extent -2.32,-1.57 2.32,1.57, body extent -1.7,-1.35 1.7,1.35, height 2.7
2512 [mm] "Chip Resistor, Body 6.3x3.2mm, IPC Medium Density"
  rect 1.3x3.4 smd: 1(-2.95,0) 2(2.95,0)
  silkscreen extent -1.9,-1.6 1.9,1.6, body extent -3.22,-1.67 3.22,1.67, height 0.71
7343-43 [mm] "Medium density IPC based on Kemet T495 series"
  rect 2.55x2.45 smd: 1(-3.025,0) 2(3.025,0)
  silkscreen extent -4.56,-2.3 3.8,2.3, body extent -3.8,-2.3 3.8,2.3, height 4.3
7361-38 [mm] "Medium density IPC based on AVX dimensions for TPS series"
  rect 2.55x3.2 smd: 1(-2.975,0) 2(2.975,0)
  silkscreen extent -4.51,-3.2 3.75,3.2, body extent -3.75,-3.15 3.75,3.15, height 3.8
DCA0056M-MFG [mm]
  rrect33% 1.55x0.3 smd paste+0 mask+0: 1(-3.75,6.75) 2(-3.75,6.25) 3(-3.75,5.75) 4(-3.75,5.25) 5(-3.75,4.75) 6(-3.75,4.25) 7(-3.75,3.75) 8(-3.75,3.25) 9(-3.75,2.75) 10(-3.75,2.25) 11(-3.75,1.75) 12(-3.75,1.25) 13(-3.75,0.75) 14(-3.75,0.25) 15(-3.75,-0.25) 16(-3.75,-0.75) 17(-3.75,-1.25) 18(-3.75,-1.75) 19(-3.75,-2.25) 20(-3.75,-2.75) 21(-3.75,-3.25) 22(-3.75,-3.75) 23(-3.75,-4.25) 24(-3.75,-4.75) 25(-3.75,-5.25) 26(-3.75,-5.75) 27(-3.75,-6.25) 28(-3.75,-6.75) 29(3.75,-6.75) 30(3.75,-6.25) 31(3.75,-5.75) 32(3.75,-5.25) 33(3.75,-4.75) 34(3.75,-4.25) 35(3.75,-3.75) 36(3.75,-3.25) 37(3.75,-2.75) 38(3.75,-2.25) 39(3.75,-1.75) 40(3.75,-1.25) 41(3.75,-0.75) 42(3.75,-0.25) 43(3.75,0.25) 44(3.75,0.75) 45(3.75,1.25) 46(3.75,1.75) 47(3.75,2.25) 48(3.75,2.75) 49(3.75,3.25) 50(3.75,3.75) 51(3.75,4.25) 52(3.75,4.75) 53(3.75,5.25) 54(3.75,5.75) 55(3.75,6.25) 56(3.75,6.75)
  rrect2% 5.1x6.75 smd paste-1000 mask-1000: 57(0,3.625) 58(0,-3.625)
  silkscreen extent -5.22,-7.42 3.1,7.42, body extent -4.62,-7.15 4.62,7.15, height 0.25
FCC_disclaimer [mil]
FP-63554-R01_SMT_XFRMR_24MM0_20MM0-MFG [mm]
  rrect3% 3.6x3.6 smd paste+0 mask+0: 1(-9.75,3.81) 2(-9.75,-3.81)
  rrect3% 3x3 smd paste+0 mask+0: 3(10.05,-6.35) 4(10.05,6.35)
  silkscreen extent -12.72,-10 12,10, body extent -12.1,-10.1 12.1,10.1, height 0.25
FP-BAT46GWJ_SOD-123-MFG [mm]
  rrect11% 0.91x1.22 smd paste-1000 mask+0: 1(-1.635,0) 2(1.635,0)
  silkscreen extent -2.82,-0.85 0.8,0.85, body extent -2.29,-1.05 2.29,1.05, height 0.25
FP-CP-D1549-BZ_SMT_XFRMR_29MM46_26MM67-MFG [mm]
  round 2.79 smd paste+0 mask+0: 1(-12.7,7.95) 2(-12.7,4.77) 5(-12.7,-4.77) 6(-12.7,-7.95)
  round 3.3 smd paste+0 mask+0: 7(12.7,-7.62) 9(12.7,0) 11(12.7,7.62)
  silkscreen extent -15.45,-13.33 14.73,13.33, body extent -14.83,-13.43 14.83,13.43, height 0.25
FP-CRM2512-FX-1002ELF_2512-MFG [mm]
  rrect4% 2.45x3.7 smd paste+0 mask+0: 1(-2.575,0) 2(2.575,0)
  silkscreen extent -0.97,-1.65 0.97,1.65, body extent -3.9,-1.95 3.9,1.95, height 0.25
FP-EPC7018GC_FSMD-G-MFG [mm]
  rrect11% 2.184x0.914 smd paste+0 mask+0: 1(2.87,2.286) 2(-2.87,2.286) 5(0,2.286)
  rrect5% 7.95x2.057 smd paste+0 mask+0: 3(0,-1.714)
  rrect6% 7.95x1.575 smd paste+0 mask+0: 4(0,0.686)
  silkscreen extent -4.08,-3.25 4.77,3.25, body extent -4.18,-2.96 4.18,2.96, height 0.25
FP-SS1H20LW_SOD-123W-MFG [mm]
  rrect8% 1.2x1.4 smd paste+0 mask+0: 1(-1.55,0) 2(1.55,0)
  silkscreen extent -2.82,-0.95 0.58,0.95, body extent -2.25,-1.05 2.25,1.05, height 0.25
IEC_Caution_Small [mil]
  silkscreen extent -107,-93 107,92
IEC_HotSurface_Small [mil]
  silkscreen extent -107,-93 107,92
Keystone5010 [mil] "Keystone Multipurpose loops"
  round 87 hole 63: 1(0,0)
  silkscreen extent -70,-70 70,70, body extent -63,-63 63,62, height 319
Keystone5011 [mil] "Keystone Multipurpose loops"
  round 87 hole 63: 1(0,0)
  silkscreen extent -70,-70 70,70, body extent -63,-63 63,62, height 319
KEYSTONE_4824 [mil] "HEX STANDOFF 6-32 NYLON 1-1/2\""
  round 1 on Mech3: 0(0,0)
  round 152 hole 152 unplated: MH(0,0)
  silkscreen extent -151,-151 151,151, body extent -144,-125 144,125, height 1500
LPD4012 [mil] "Coilcraft"
  round 10 smd: 1(-59,55) 2(-55,-59) 3(59,-55) 4(55,59)
  Top Layer region: -89,-24 -89,-55 -55,-89 -24,-89 -24,-60 -60,-24
  Top Layer region: 89,-24 89,-55 55,-89 24,-89 24,-60 60,-24
  Top Layer region: 89,24 89,55 55,89 24,89 24,60 60,24
  Top Layer region: -89,24 -89,55 -55,89 -24,89 -24,60 -60,24
  silkscreen extent -97,-97 97,97, body extent -80,-80 78,78, height 41
On-Shore_OSTT7020150 [mm] "Terminal Block, 6.35mm, 2x1, TH"
  rrect50% 2.1x2.1 hole 1.6: 1(-3.175,0)
  round 2.1 hole 1.6: 2(3.175,0)
  silkscreen extent -6.98,-8 6.35,5, body extent -6.98,-8 6.35,4.5, height 21.5
PW0024A-MFG [mm]
  rrect22% 1.5x0.45 smd paste+0 mask+0: 1(-2.9,3.575) 2(-2.9,2.925) 3(-2.9,2.275) 4(-2.9,1.625) 5(-2.9,0.975) 6(-2.9,0.325) 7(-2.9,-0.325) 8(-2.9,-0.975) 9(-2.9,-1.625) 10(-2.9,-2.275) 11(-2.9,-2.925) 12(-2.9,-3.575) 13(2.9,-3.575) 14(2.9,-2.925) 15(2.9,-2.275) 16(2.9,-1.625) 17(2.9,-0.975) 18(2.9,-0.325) 19(2.9,0.325) 20(2.9,0.975) 21(2.9,1.625) 22(2.9,2.275) 23(2.9,2.925) 24(2.9,3.575)
  silkscreen extent -4.38,-3.95 1.78,3.95, body extent -3.75,-4.2 3.75,4.2, height 0.25
SMB [mil] "Molded Diode, 2-Leads, Body 5.4x3.6mm, IPC Medium Density, based on OnSemi component dimensions"
  rect 85x107.99 smd: 1(-87.01,0) 2(87.01,0)
  silkscreen extent -155,-82 125,82, body extent -106,-71 106,71, height 91
SOD-123 [mm] "On Semi recommended land pattern"
  rect 0.915x1.22 smd: 1(-1.637,0) 2(1.637,0)
  silkscreen extent -2.74,-1.17 2.03,1.17, body extent -1.93,-0.9 1.93,0.9, height 1.35
SOD-123W [mm] "NXP recommended land pattern"
  rect 1.2x1.2 smd paste-0.05: 1(-1.4,0) 2(1.4,0)
  silkscreen extent -2.64,-1.14 1.68,1.14, body extent -1.85,-0.95 1.85,0.95, height 1.1
SOT-23 [mm] "SOT23, 3-Leads, Body 2.9x1.3mm, Pitch 0.95mm, Lead Span 2.5mm, IPC Medium Density"
  rrect50% 1x0.6 smd: 1(-1.2,0.95) 2(-1.2,-0.95) 3(1.2,0)
  silkscreen extent -1.62,-1.5 0.7,1.5, body extent -1.16,-1.45 1.21,1.45, height 1
WE-HCB_1890 [mm] "WURTH ELEKTRONIK"
  rect 6x6 smd: 1(-6.65,0) 2(6.65,0)
  silkscreen extent -9.7,-9.4 9.7,9.4, body extent -9.65,-9.35 9.65,9.35, height 9.2
WEEE_Minimum [mil] "WEEElie bin"
  silkscreen extent -95,-172 99,104
WURTH_61300211121 [mm] "Header, 2.54mm, 2x1, TH"
  rrect50% 1.65x1.65 hole 1.15: 1(-1.27,0)
  round 1.65 hole 1.15: 2(1.27,0)
  body extent -2.54,-1.27 2.54,1.27, height 8.54
WURTH_61300311121 [mm] "Header, 2.54mm, 3x1, TH"
  rrect50% 1.65x1.65 hole 1.15: 1(-2.54,0)
  round 1.65 hole 1.15: 2(0,0) 3(2.54,0)
  body extent -3.81,-1.27 3.81,1.27, height 8.54
WURTH_61300611121 [mm] "Header, 2.54mm, 6x1, TH"
  rrect50% 1.65x1.65 hole 1.15: 1(-6.35,0)
  round 1.65 hole 1.15: 2(-3.81,0) 3(-1.27,0) 4(1.27,0) 5(3.81,0) 6(6.35,0)
  body extent -7.62,-1.27 7.62,1.27, height 8.54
